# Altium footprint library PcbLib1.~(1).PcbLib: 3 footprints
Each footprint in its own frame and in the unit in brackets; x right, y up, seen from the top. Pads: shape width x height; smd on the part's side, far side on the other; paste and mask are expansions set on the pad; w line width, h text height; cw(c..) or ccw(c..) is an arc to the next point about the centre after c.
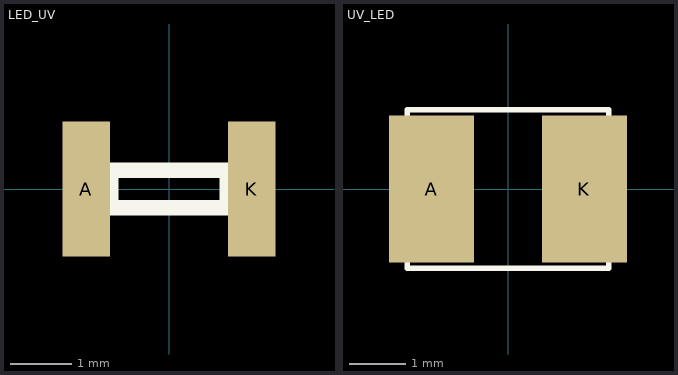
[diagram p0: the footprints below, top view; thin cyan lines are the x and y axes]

## LED_UV [mil]
pads (2):
  rect 31x87 smd: A(-53.5,0) K(53.5,0)
Top Overlay:
  lines w10: -37.5,-12 37.5,-12 37.5,12 -37.5,12 -37.5,0 -37.5,-12

## PCBComponent_1 [mm]

## UV_LED [mm]
pads (2):
  rect 1.5x2.6 smd: A(-1.35,0) K(1.35,0)
Top Overlay:
  lines w0.1: -1.778,-1.4 1.778,-1.4 1.778,1.4 -1.778,1.4 -1.778,-1.4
